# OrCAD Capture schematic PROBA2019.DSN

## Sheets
1 PAGE2
2 PAGE1: size A
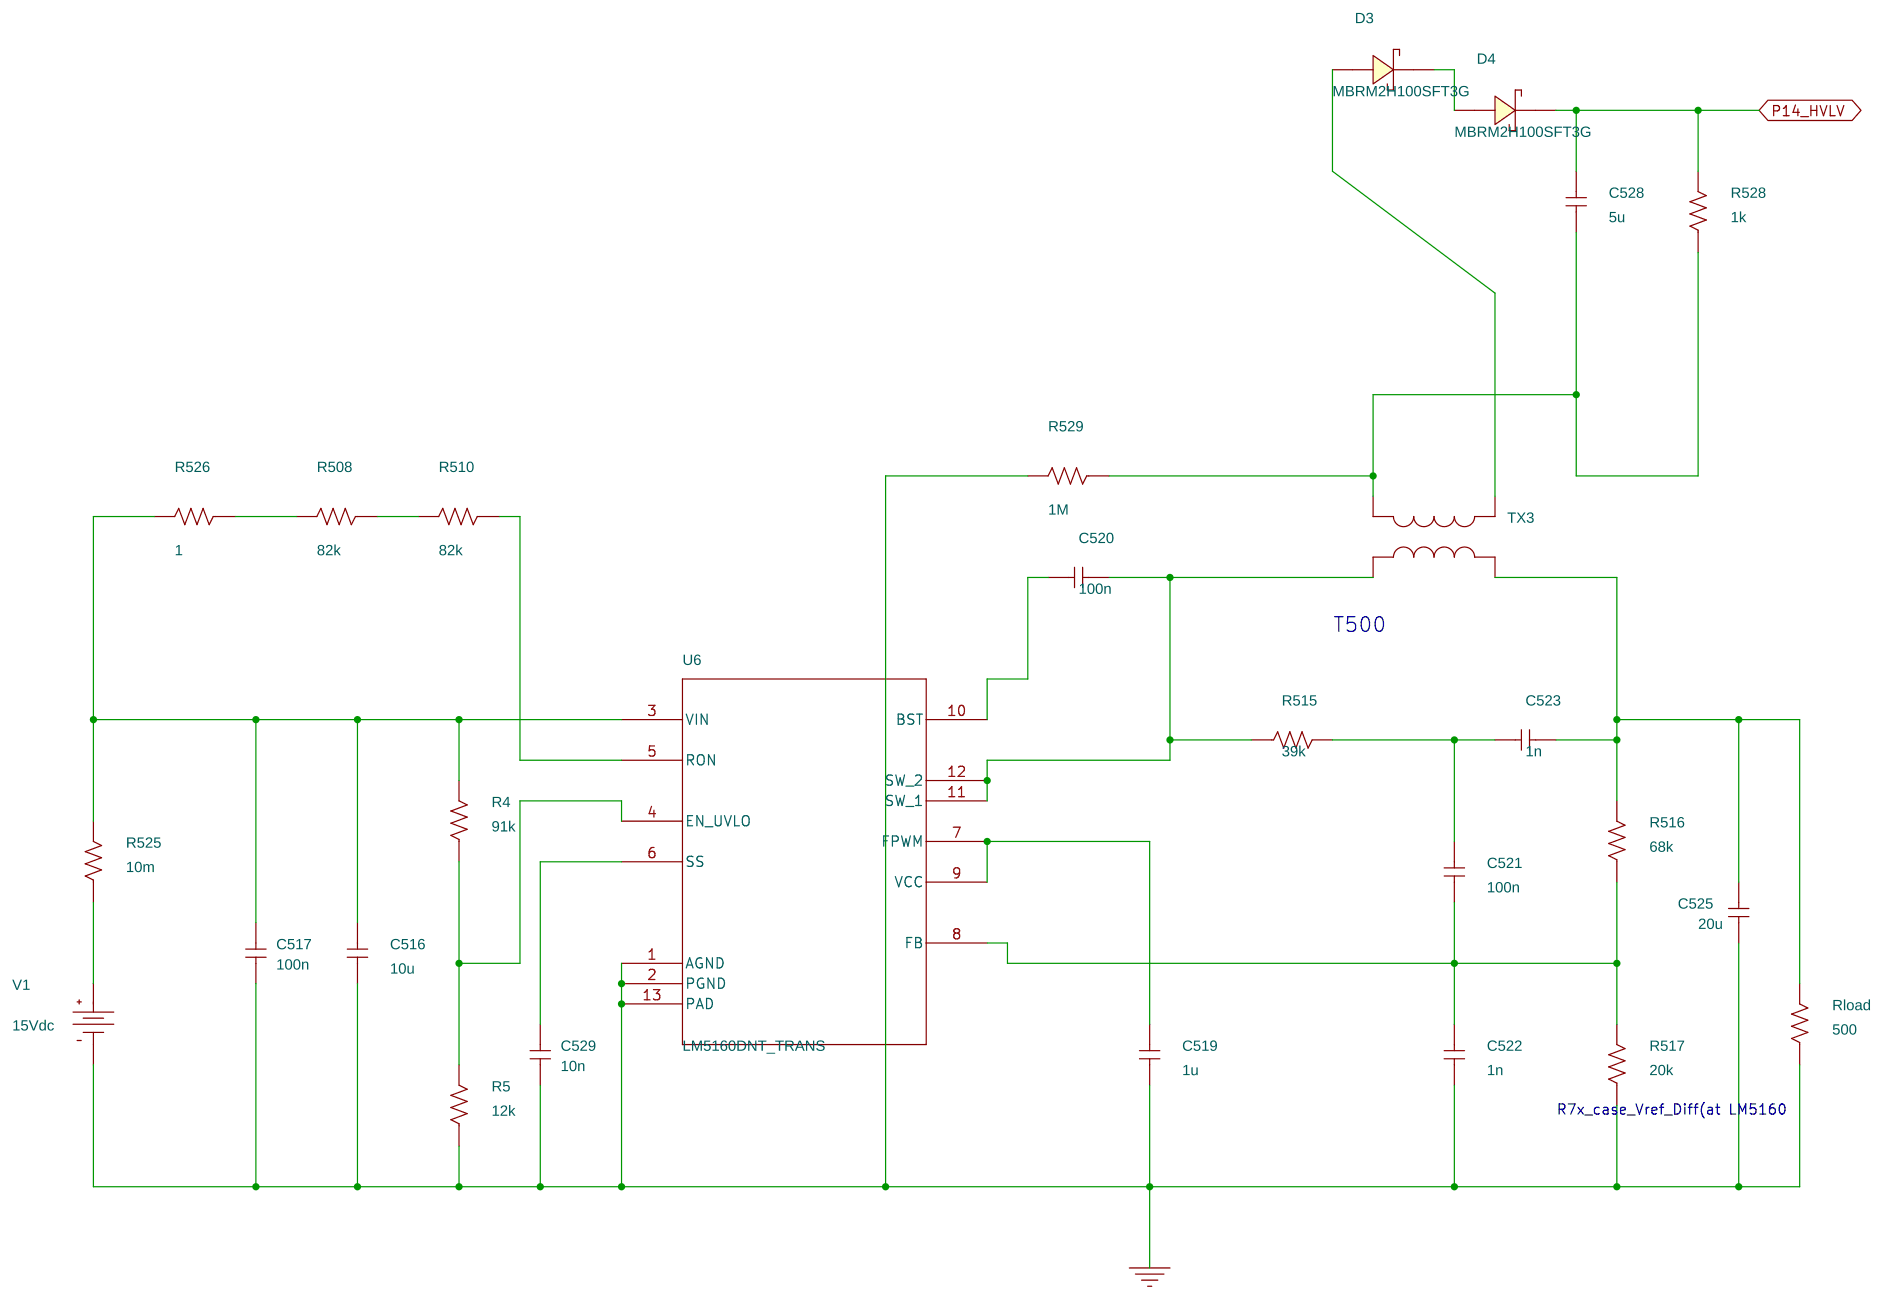
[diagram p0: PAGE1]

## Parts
C516  10u  [RAD/CK05]
C517  100n  [RAD/CK05]
C519  1u  [RAD/CK05]
C520  100n  [RAD/CK05]
C521  100n  [RAD/CK05]
C522  1n  [RAD/CK05]
C523  1n  [RAD/CK05]
C525  20u  [RAD/CK05]
C528  5u  [RAD/CK05]
C529  10n  [RAD/CK05]
D3  MBRM2H100SFT3G  [D0216AA]
D4  MBRM2H100SFT3G  [D0216AA]
R4  91k  [AX/RC05]
R5  12k  [AX/RC05]
R508  82k  [AX/RC05]
R510  82k  [AX/RC05]
R515  39k  [AX/RC05]
R516  68k  [AX/RC05]
R517  20k  [AX/RC05]
R525  10m  [AX/RC05]
R526  1  [AX/RC05]
R528  1k  [AX/RC05]
R529  1M  [AX/RC05]
Rload  500  [AX/RC05]
TX3  XFRM_LINEAR
U6  LM5160DNT_TRANS  [DNT0012B]
V1  VDC

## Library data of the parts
C516 C517 C519-C523 C525 C528 C529 = C
D3 D4 = MBRM2H100SFT3G
R4 R5 R508 R510 R515-R517 R525 R526 R528 R529 Rload = R
TX3 = XFRM_LINEAR: L1_VALUE: 30uH; L2_VALUE: 30uH
U6 = LM5160DNT_TRANS
V1 = VDC: DC: 15Vdc

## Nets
0: C516.1 C517.1 C519.1 C522.1 C525.1 C529.1 R5.1 R517.1 R529.2 Rload.1 U6.1(AGND) U6.2(PGND) U6.13(PAD) V1.1(-)
P14_HVLV: C528.2 D4.1(C) R528.2
N40150: C516.2 C517.2 R4.2 R525.2 R526.2 U6.3(VIN)
N40158: R508.1 R510.2
N40164: R510.1 U6.5(RON)
N40234: C520.1 U6.10(BST)
N40244: C520.2 R515.1 TX3.1 U6.11(SW_1) U6.12(SW_2)
N40258: C523.2 C525.2 R516.2 Rload.2 TX3.2
N40450: C521.2 C523.1 R515.2
N40542: C519.2 U6.7(FPWM) U6.9(VCC)
N40562: R4.1 R5.2 U6.4(EN_UVLO)
N40592: C521.1 C522.2 R516.1 R517.2 U6.8(FB)
N40596: R525.1 V1.0(+)
N45375: R508.2 R526.1
N47197: D3.2(A) TX3.4
N47203: D3.1(C) D4.2(A)
N47343: C528.1 R528.1 R529.1 TX3.3
N54758: C529.2 U6.6(SS)

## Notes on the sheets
sheet 2
- T500
- R7x_case_Vref_Diff(at LM5160
